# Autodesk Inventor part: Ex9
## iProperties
Author: Administrator
Created: 2001-01
Part Number: Ex9
Document SubType Name: Modeling
Designer: Administrator
Control State: 0
Master: False
Checked Out: False
PropertySet Name: Design Tracking Control
Shininess: 0.0
PropertySet Name: _Private Model Information
Density: 0.0
Volumn: 0.0
Area: 0.0
PropertySet Name: Model Information
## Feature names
1. Extrusion1
2. Extrusion2
3. Extrusion3
4. Hole1
5. Fillet1
6. Hole2
7. Circular Pattern1
8. Chamfer1
